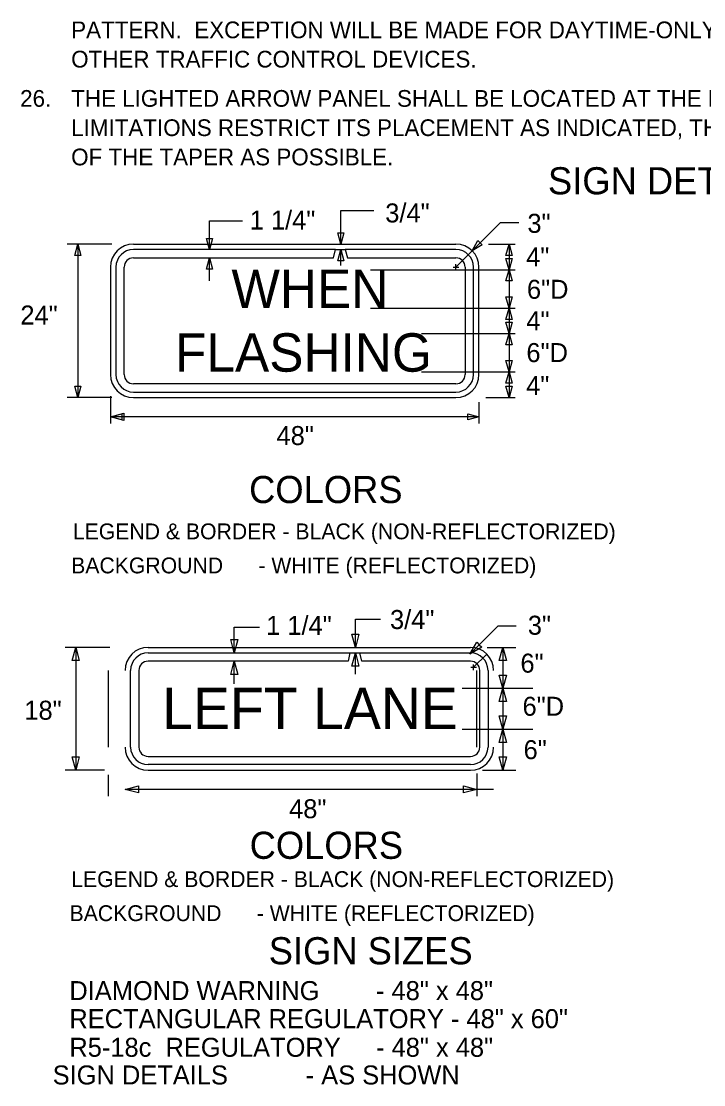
# Model space of a CAD drawing. Extents: x 15262 to 18126, y 1908 to 6555.
# Drawn here: x 17443.6 to 17745, y 2193.3 to 2663.3 of the extents above; entities that cross this region are included whole.
import ezdxf

# ---------------------------------------------------------------- set-up
doc = ezdxf.new("R2010")
doc.units = 0
for name, color, linetype in [('MT_SCRATCH_LEVEL_A', 7, 'Continuous'), ('TYPICAL_EX', 7, 'Continuous'), ('TYPICAL_TEXT_DIMEN_EX', 7, 'Continuous'), ('TYPICAL_TEXT_DIMEN_PR', 7, 'Continuous')]:
    doc.layers.add(name, color=color, linetype=linetype)

msp = doc.modelspace()

# ---------------------------------------------------------------- linework, layer by layer
at = {"layer": 'MT_SCRATCH_LEVEL_A'}
for p, q in [((17584.74, 2579.66), (17599.29, 2579.66)), ((17526.79, 2575.12), (17541.34, 2575.12)), ((17642.75, 2561.91), (17655.1, 2574.32)), ((17663.3, 2574.32), (17655.1, 2574.32)), ((17635.6, 2554.73), (17642.75, 2561.91)), ((17634.35, 2554.73), (17636.85, 2554.73)), ((17635.6, 2553.51), (17635.6, 2556.01)), ((17483.01, 2497.7), (17483.01, 2485.62)), ((17645.77, 2494.97), (17645.77, 2485.62)), ((17645.77, 2488.53), (17483.01, 2488.53)), ((17591.18, 2399.05), (17602.32, 2399.05)), ((17537.72, 2395.58), (17548.86, 2395.58)), ((17641.74, 2383.67), (17654.08, 2396.05)), ((17662.25, 2396.05), (17654.08, 2396.05)), ((17643.39, 2377.85), (17649.19, 2383.67)), ((17643.39, 2376.63), (17643.39, 2379.11)), ((17642.1, 2377.85), (17644.64, 2377.85)), ((17482.04, 2330.34), (17482.04, 2320.93)), ((17644.76, 2330.92), (17644.76, 2320.93)), ((17652.2, 2323.85), (17489.48, 2323.85))]:
    msp.add_line(p, q, dxfattribs=at)
at = {"layer": 'TYPICAL_EX'}
for p, q in [((17493.19, 2564.87), (17635.6, 2564.87)), ((17582.33, 2562.43), (17493.19, 2562.43)), ((17581.51, 2558.77), (17582.33, 2562.43)), ((17582.33, 2562.43), (17586.74, 2562.43)), ((17635.6, 2562.43), (17586.74, 2562.43)), ((17586.74, 2562.43), (17587.68, 2558.77)), ((17493.19, 2558.77), (17581.51, 2558.77)), ((17587.68, 2558.77), (17635.6, 2558.77)), ((17483.01, 2554.7), (17483.01, 2507.22)), ((17485.45, 2554.7), (17485.45, 2507.22)), ((17489.12, 2507.22), (17489.12, 2554.7)), ((17639.67, 2554.7), (17639.67, 2507.22)), ((17643.33, 2507.22), (17643.33, 2554.7)), ((17645.77, 2507.22), (17645.77, 2554.7)), ((17635.6, 2503.15), (17493.19, 2503.15)), ((17493.19, 2499.49), (17635.6, 2499.49)), ((17493.19, 2497.04), (17635.6, 2497.04)), ((17499.65, 2386.63), (17642.03, 2386.63)), ((17499.65, 2384.19), (17588.77, 2384.19)), ((17588.77, 2384.19), (17587.96, 2380.53)), ((17588.77, 2384.19), (17593.18, 2384.19)), ((17587.96, 2380.53), (17499.65, 2380.53)), ((17482.04, 2376.46), (17482.04, 2342.53)), ((17491.92, 2342.53), (17491.92, 2376.46)), ((17495.58, 2376.46), (17495.58, 2342.53)), ((17644.76, 2342.53), (17644.76, 2376.46)), ((17499.65, 2338.46), (17642.03, 2338.46)), ((17642.03, 2334.8), (17499.65, 2334.8)), ((17499.65, 2332.36), (17642.03, 2332.36))]:
    msp.add_line(p, q, dxfattribs=at)
for centre, radius, start, end in [((17493.18, 2554.7), 10.17, 90, 180), ((17493.18, 2554.7), 7.73, 90, 180), ((17635.6, 2554.7), 10.17, 0, 90), ((17635.6, 2554.7), 7.73, 0, 90), ((17493.18, 2554.7), 4.07, 90, 180), ((17635.6, 2554.7), 4.07, 0, 90), ((17493.18, 2507.21), 10.17, 180, 270), ((17493.18, 2507.21), 7.73, 180, 270), ((17493.18, 2507.21), 4.07, 180, 270), ((17635.6, 2507.21), 10.17, 270, 0), ((17635.6, 2507.21), 4.07, 270, 0), ((17635.6, 2507.21), 7.73, 270, 0), ((17499.65, 2376.46), 10.17, 90, 180), ((17499.65, 2376.46), 7.73, 90, 180), ((17642.03, 2376.46), 10.17, 0, 90), ((17499.65, 2376.46), 4.07, 90, 180), ((17499.65, 2342.53), 10.17, 180, 270), ((17499.65, 2342.53), 7.73, 180, 270), ((17499.65, 2342.53), 4.07, 180, 270), ((17642.03, 2342.53), 10.17, 270, 0), ((17642.03, 2342.53), 7.73, 270, 0), ((17642.03, 2342.53), 4.07, 270, 0)]:
    msp.add_arc(centre, radius, start, end, dxfattribs=at)
at = {"layer": 'TYPICAL_TEXT_DIMEN_PR'}
for p, q in [((17584.74, 2564.87), (17584.74, 2579.66)), ((17526.79, 2562.43), (17526.79, 2575.12)), ((17526.79, 2562.43), (17525.46, 2567.41)), ((17525.46, 2567.41), (17526.79, 2567.41)), ((17526.79, 2567.41), (17528.13, 2567.41)), ((17528.13, 2567.41), (17526.79, 2562.43)), ((17584.74, 2564.87), (17583.4, 2569.85)), ((17583.4, 2569.85), (17584.74, 2569.85)), ((17584.74, 2569.85), (17586.07, 2569.85)), ((17586.07, 2569.85), (17584.74, 2564.87)), ((17642.75, 2561.91), (17645.32, 2566.39)), ((17645.32, 2566.39), (17646.27, 2565.45)), ((17483.67, 2564.87), (17463.92, 2564.87)), ((17467.31, 2559.89), (17468.65, 2564.87)), ((17468.65, 2564.87), (17468.65, 2497.04)), ((17468.65, 2564.87), (17469.98, 2559.89)), ((17583.4, 2557.45), (17584.74, 2562.43)), ((17584.74, 2555.4), (17584.74, 2562.43)), ((17584.74, 2562.43), (17586.07, 2557.45)), ((17647.21, 2564.5), (17642.75, 2561.91)), ((17646.27, 2565.45), (17647.21, 2564.5)), ((17650.04, 2564.87), (17661.73, 2564.87)), ((17657.7, 2559.89), (17659.03, 2564.87)), ((17659.03, 2564.87), (17659.03, 2553.55)), ((17659.03, 2564.87), (17660.37, 2559.89)), ((17468.65, 2559.89), (17467.31, 2559.89)), ((17469.98, 2559.89), (17468.65, 2559.89)), ((17525.46, 2553.78), (17526.79, 2558.77)), ((17526.79, 2548.68), (17526.79, 2558.77)), ((17526.79, 2558.77), (17528.13, 2553.78)), ((17584.74, 2557.45), (17583.4, 2557.45)), ((17586.07, 2557.45), (17584.74, 2557.45)), ((17659.03, 2559.89), (17657.7, 2559.89)), ((17659.03, 2553.55), (17657.7, 2558.53)), ((17657.7, 2558.53), (17659.03, 2558.53)), ((17660.37, 2559.89), (17659.03, 2559.89)), ((17659.03, 2558.53), (17660.37, 2558.53)), ((17660.37, 2558.53), (17659.03, 2553.55)), ((17526.79, 2553.78), (17525.46, 2553.78)), ((17528.13, 2553.78), (17526.79, 2553.78)), ((17597.83, 2553.55), (17661.73, 2553.55)), ((17657.7, 2548.57), (17659.03, 2553.55)), ((17659.03, 2553.55), (17659.03, 2536.57)), ((17659.03, 2553.55), (17660.37, 2548.57)), ((17659.03, 2548.57), (17657.7, 2548.57)), ((17660.37, 2548.57), (17659.03, 2548.57)), ((17659.03, 2536.57), (17657.7, 2541.55)), ((17657.7, 2541.55), (17659.03, 2541.55)), ((17659.03, 2541.55), (17660.37, 2541.55)), ((17660.37, 2541.55), (17659.03, 2536.57)), ((17597.83, 2536.57), (17661.73, 2536.57)), ((17657.7, 2531.59), (17659.03, 2536.57)), ((17659.03, 2536.57), (17659.03, 2525.34)), ((17659.03, 2536.57), (17660.37, 2531.59)), ((17659.03, 2531.59), (17657.7, 2531.59)), ((17659.03, 2525.34), (17657.7, 2530.33)), ((17657.7, 2530.33), (17659.03, 2530.33)), ((17659.03, 2525.34), (17657.7, 2530.33)), ((17657.7, 2530.33), (17659.03, 2530.33)), ((17660.37, 2531.59), (17659.03, 2531.59)), ((17659.03, 2530.33), (17660.37, 2530.33)), ((17660.37, 2530.33), (17659.03, 2525.34)), ((17659.03, 2530.33), (17660.37, 2530.33)), ((17660.37, 2530.33), (17659.03, 2525.34)), ((17620.44, 2525.34), (17661.73, 2525.34)), ((17657.7, 2520.36), (17659.03, 2525.34)), ((17659.03, 2525.34), (17659.03, 2508.36)), ((17659.03, 2525.34), (17660.37, 2520.36)), ((17659.03, 2520.36), (17657.7, 2520.36)), ((17660.37, 2520.36), (17659.03, 2520.36)), ((17659.03, 2508.36), (17657.7, 2513.35)), ((17657.7, 2513.35), (17659.03, 2513.35)), ((17659.03, 2508.36), (17657.7, 2513.35)), ((17657.7, 2513.35), (17659.03, 2513.35)), ((17659.03, 2513.35), (17660.37, 2513.35)), ((17660.37, 2513.35), (17659.03, 2508.36)), ((17659.03, 2513.35), (17660.37, 2513.35)), ((17660.37, 2513.35), (17659.03, 2508.36)), ((17620.44, 2508.36), (17661.73, 2508.36)), ((17657.7, 2503.38), (17659.03, 2508.36)), ((17659.03, 2508.36), (17659.03, 2497.04)), ((17659.03, 2508.36), (17660.37, 2503.38)), ((17468.65, 2497.04), (17467.31, 2502.03)), ((17467.31, 2502.03), (17468.65, 2502.03)), ((17468.65, 2502.03), (17469.98, 2502.03)), ((17469.98, 2502.03), (17468.65, 2497.04)), ((17659.03, 2503.38), (17657.7, 2503.38)), ((17659.03, 2497.04), (17657.7, 2502.03)), ((17657.7, 2502.03), (17659.03, 2502.03)), ((17660.37, 2503.38), (17659.03, 2503.38)), ((17659.03, 2502.03), (17660.37, 2502.03)), ((17660.37, 2502.03), (17659.03, 2497.04)), ((17483.67, 2497.04), (17463.92, 2497.04)), ((17648.79, 2497.04), (17661.73, 2497.04)), ((17483.01, 2488.53), (17488.87, 2490.1)), ((17483.01, 2488.53), (17488, 2489.87)), ((17488.87, 2486.96), (17483.01, 2488.53)), ((17488, 2487.2), (17483.01, 2488.53)), ((17488, 2489.87), (17488, 2488.53)), ((17488, 2488.53), (17488, 2487.2)), ((17488.87, 2490.1), (17488.87, 2488.53)), ((17488.87, 2488.53), (17488.87, 2486.96)), ((17640.79, 2488.53), (17640.79, 2489.87)), ((17640.79, 2489.87), (17645.77, 2488.53)), ((17645.77, 2488.53), (17640.79, 2487.2)), ((17640.79, 2487.2), (17640.79, 2488.53)), ((17591.18, 2386.63), (17591.18, 2399.05)), ((17537.72, 2384.19), (17537.72, 2395.58)), ((17591.18, 2386.63), (17589.61, 2392.49)), ((17589.61, 2392.49), (17591.18, 2392.49)), ((17591.18, 2392.49), (17592.75, 2392.49)), ((17592.75, 2392.49), (17591.18, 2386.63)), ((17537.72, 2384.19), (17536.15, 2390.05)), ((17536.15, 2390.05), (17537.72, 2390.05)), ((17537.72, 2390.05), (17539.3, 2390.05)), ((17539.3, 2390.05), (17537.72, 2384.19)), ((17641.74, 2383.67), (17644.77, 2388.93)), ((17644.77, 2388.93), (17645.88, 2387.83)), ((17645.88, 2387.83), (17646.99, 2386.72)), ((17482.68, 2386.63), (17462.95, 2386.63)), ((17466.09, 2380.77), (17467.66, 2386.63)), ((17467.66, 2386.63), (17467.66, 2332.36)), ((17467.66, 2386.63), (17469.24, 2380.77)), ((17499.65, 2384.19), (17588.77, 2384.19)), ((17588.77, 2384.19), (17587.96, 2380.53)), ((17589.61, 2378.33), (17591.18, 2384.19)), ((17591.18, 2374.83), (17591.18, 2384.19)), ((17591.18, 2384.19), (17592.75, 2378.33)), ((17594.1, 2380.53), (17593.18, 2384.19)), ((17593.18, 2384.19), (17642.03, 2384.19)), ((17646.99, 2386.72), (17641.74, 2383.67)), ((17649.38, 2386.63), (17662.08, 2386.63)), ((17654.71, 2380.77), (17656.28, 2386.63)), ((17656.28, 2386.63), (17656.28, 2368.54)), ((17656.28, 2386.63), (17657.85, 2380.77)), ((17467.66, 2380.77), (17466.09, 2380.77)), ((17469.24, 2380.77), (17467.66, 2380.77)), ((17587.96, 2380.53), (17499.65, 2380.53)), ((17536.15, 2374.67), (17537.72, 2380.53)), ((17537.72, 2370.54), (17537.72, 2380.53)), ((17537.72, 2380.53), (17539.3, 2374.67)), ((17591.18, 2378.33), (17589.61, 2378.33)), ((17592.75, 2378.33), (17591.18, 2378.33)), ((17642.03, 2380.53), (17594.1, 2380.53)), ((17656.28, 2380.77), (17654.71, 2380.77)), ((17657.85, 2380.77), (17656.28, 2380.77)), ((17491.92, 2342.53), (17491.92, 2376.46)), ((17495.58, 2376.46), (17495.58, 2342.53)), ((17537.72, 2374.67), (17536.15, 2374.67)), ((17539.3, 2374.67), (17537.72, 2374.67)), ((17646.1, 2342.53), (17646.1, 2376.46)), ((17649.76, 2376.46), (17649.76, 2342.53)), ((17656.28, 2368.54), (17654.71, 2374.4)), ((17654.71, 2374.4), (17656.28, 2374.4)), ((17656.28, 2374.4), (17657.85, 2374.4)), ((17657.85, 2374.4), (17656.28, 2368.54)), ((17638.39, 2368.54), (17669.52, 2368.54)), ((17654.71, 2362.68), (17656.28, 2368.54)), ((17656.28, 2368.54), (17656.28, 2350.45)), ((17656.28, 2368.54), (17657.85, 2362.68)), ((17656.28, 2362.68), (17654.71, 2362.68)), ((17657.85, 2362.68), (17656.28, 2362.68)), ((17656.28, 2350.45), (17654.71, 2356.31)), ((17654.71, 2356.31), (17656.28, 2356.31)), ((17656.28, 2356.31), (17657.85, 2356.31)), ((17657.85, 2356.31), (17656.28, 2350.45)), ((17638.39, 2350.45), (17669.52, 2350.45)), ((17654.71, 2344.59), (17656.28, 2350.45)), ((17656.28, 2350.45), (17656.28, 2332.36)), ((17656.28, 2350.45), (17657.85, 2344.59)), ((17656.28, 2344.59), (17654.71, 2344.59)), ((17657.85, 2344.59), (17656.28, 2344.59)), ((17467.66, 2332.36), (17466.09, 2338.22)), ((17466.09, 2338.22), (17467.66, 2338.22)), ((17467.66, 2338.22), (17469.24, 2338.22)), ((17469.24, 2338.22), (17467.66, 2332.36)), ((17499.65, 2338.46), (17642.03, 2338.46)), ((17656.28, 2332.36), (17654.71, 2338.22)), ((17654.71, 2338.22), (17656.28, 2338.22)), ((17656.28, 2338.22), (17657.85, 2338.22)), ((17657.85, 2338.22), (17656.28, 2332.36)), ((17480.41, 2332.36), (17462.95, 2332.36)), ((17642.03, 2334.8), (17499.65, 2334.8)), ((17647.38, 2332.36), (17662.08, 2332.36)), ((17489.48, 2323.85), (17495.34, 2325.42)), ((17495.34, 2322.28), (17489.48, 2323.85)), ((17495.34, 2325.42), (17495.34, 2323.85)), ((17495.34, 2323.85), (17495.34, 2322.28)), ((17638.9, 2323.85), (17638.9, 2325.42)), ((17638.9, 2325.42), (17644.76, 2323.85)), ((17644.76, 2323.85), (17638.9, 2322.28)), ((17638.9, 2322.28), (17638.9, 2323.85))]:
    msp.add_line(p, q, dxfattribs=at)
for centre, radius, start, end in [((17499.65, 2376.46), 7.73, 90, 180), ((17642.03, 2376.46), 7.73, 0, 90), ((17499.65, 2376.46), 4.07, 90, 180), ((17642.03, 2376.46), 4.07, 0, 90), ((17499.65, 2342.53), 7.73, 180, 270), ((17499.65, 2342.53), 4.07, 180, 270), ((17642.03, 2342.53), 4.07, 270, 0), ((17642.03, 2342.53), 7.73, 270, 0)]:
    msp.add_arc(centre, radius, start, end, dxfattribs=at)

# ---------------------------------------------------------------- texts
at = {"layer": 'TYPICAL_TEXT_DIMEN_EX'}
for s, height, p in [('WHEN   ', 16.968, (17536.43, 2536.66)), ('FLASHING', 16.968, (17511.52, 2508.48)), ('LEFT LANE', 18.308, (17505.84, 2350.51))]:
    msp.add_text(s, height=height, dxfattribs=at).set_placement(p)
at = {"layer": 'TYPICAL_TEXT_DIMEN_PR'}
for s, height, p in [('PATTERN.  EXCEPTION WILL BE MADE FOR DAYTIME-ONLY TRAFFIC PATTERNS THAT ARE ADEQUATELY DELINEATED BY', 7.392, (17465.67, 2655.84)), ('OTHER TRAFFIC CONTROL DEVICES.', 7.392, (17465.67, 2642.9)), ('26.', 7.392, (17443.13, 2625.55)), ('THE LIGHTED ARROW PANEL SHALL BE LOCATED AT THE BEGINNING OF THE TAPER AS SHOWN.  WHEN PHYSICAL', 7.392, (17465.67, 2625.55)), ('LIMITATIONS RESTRICT ITS PLACEMENT AS INDICATED, THEN IT SHALL BE PLACED AS CLOSE TO THE BEGINNING', 7.392, (17465.67, 2612.61)), ('OF THE TAPER AS POSSIBLE.', 7.392, (17465.67, 2599.67)), ('SIGN DETAILS', 12, (17676.24, 2586.85)), ('3/4"', 8.4, (17604.38, 2574.44)), ('1 1/4"', 8.4, (17544.52, 2571.3)), ('3"', 8.4, (17667.16, 2569.85)), ('4"', 8.4, (17666.61, 2555.08)), ('6"D', 8.4, (17666.95, 2540.69)), ('24"', 8.4, (17443.23, 2529.32)), ('4"', 8.4, (17666.69, 2526.82)), ('6"D', 8.4, (17666.72, 2512.72)), ('4"', 8.4, (17666.61, 2498.19)), ('48"', 8.4, (17556.36, 2476.04)), ('COLORS', 12, (17544.24, 2450.4)), ('LEGEND & BORDER - BLACK (NON-REFLECTORIZED)', 7, (17466.4, 2434.4)), ('BACKGROUND      - WHITE (REFLECTORIZED)', 7, (17465.67, 2419.35)), ('3/4"', 8.4, (17606.48, 2394.74)), ('1 1/4"', 8.4, (17551.77, 2392.16)), ('3"', 8.4, (17667.34, 2392.22)), ('6"', 8.4, (17664.08, 2375.47)), ('6"D', 8.4, (17665.01, 2356.41)), ('18"', 8.4, (17444.99, 2354.65)), ('6"', 8.4, (17665.47, 2337.23)), ('48"', 8.4, (17561.91, 2311.12)), ('COLORS', 12, (17544.48, 2293.17)), ('LEGEND & BORDER - BLACK (NON-REFLECTORIZED)', 7, (17465.67, 2280.71)), ('BACKGROUND      - WHITE (REFLECTORIZED)', 7, (17464.95, 2265.66)), ('SIGN SIZES', 12, (17552.91, 2246.56)), ('DIAMOND WARNING        - 48" x 48"', 8.4, (17464.87, 2230.74)), ('RECTANGULAR REGULATORY - 48" x 60"', 8.4, (17464.87, 2218.34)), ('R5-18c  REGULATORY     - 48" x 48"', 8.4, (17464.87, 2205.69)), ('SIGN DETAILS           - AS SHOWN', 8.4, (17457.5, 2193.46))]:
    msp.add_text(s, height=height, dxfattribs=at).set_placement(p)

doc.saveas('drawing.dxf')
